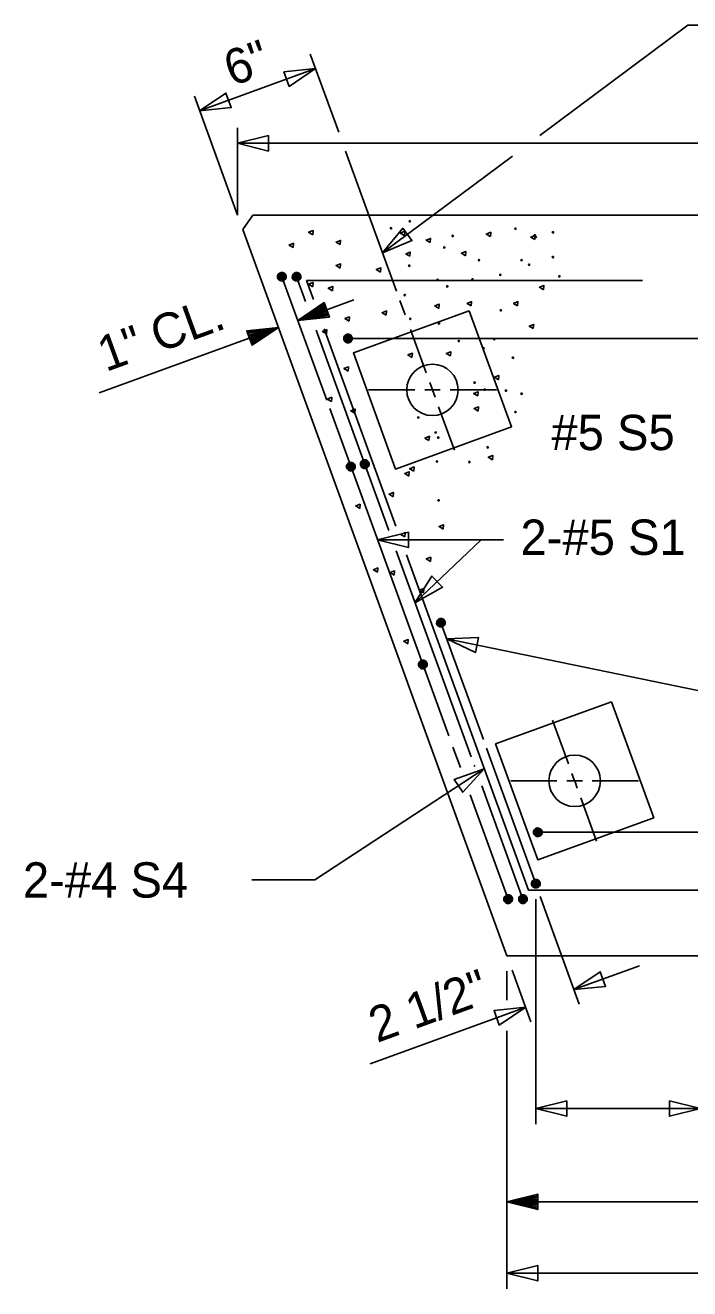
# Model space of a CAD drawing. Extents: x -408 to -23, y -15 to 117.
# Drawn here: x -111.83 to -109.13, y 76.34 to 81.46 of the extents above; entities that cross this region are included whole.
import ezdxf

# ---------------------------------------------------------------- set-up
doc = ezdxf.new("R2010")
doc.units = 0
for name, color, linetype in [('Arrowhead Terminators CELL', 7, 'Continuous'), ('Dimension Lines', 7, 'Continuous'), ('Rebar Lines', 7, 'Continuous'), ('Sup Concrete Girder Lines', 7, 'Continuous'), ('Sup Cored Slab Unit', 7, 'Continuous'), ('Text', 7, 'Continuous')]:
    doc.layers.add(name, color=color, linetype=linetype)

msp = doc.modelspace()

# ---------------------------------------------------------------- linework, layer by layer
at = {"layer": 'Arrowhead Terminators CELL'}
for points in [[(-110.6484, 81.2858), (-110.7766, 81.2724), (-110.7552, 81.2137)], [(-111.1183, 81.1148), (-110.9901, 81.1282), (-111.0115, 81.1869)], [(-110.9648, 80.9833), (-110.8398, 80.9521), (-110.8398, 81.0146)], [(-110.3768, 80.5394), (-110.2579, 80.589), (-110.2952, 80.6391)], [(-110.3973, 79.377), (-110.2722, 79.3458), (-110.2723, 79.4083)], [(-110.2459, 79.1216), (-110.1339, 79.1852), (-110.1769, 79.2304)], [(-110.1166, 78.9762), (-110.0005, 78.9204), (-109.9879, 78.9816)], [(-109.9649, 78.4494), (-110.0866, 78.407), (-110.0523, 78.3548)], [(-109.6013, 77.5554), (-109.4731, 77.5688), (-109.4945, 77.6276)], [(-109.797, 77.4842), (-109.9251, 77.4708), (-109.9038, 77.4121)], [(-109.7557, 77.0737), (-109.6307, 77.0425), (-109.6307, 77.105)], [(-109.089, 77.0737), (-109.214, 77.105), (-109.214, 77.0425)], [(-109.8729, 76.407), (-109.7479, 76.3758), (-109.7479, 76.4383)]]:
    msp.add_lwpolyline(points, close=True, dxfattribs=at)
at = {"layer": 'Dimension Lines'}
for p, q in [((-110.5546, 81.0279), (-110.6699, 81.3445)), ((-110.6484, 81.2858), (-111.1183, 81.1148)), ((-110.9648, 80.6929), (-111.1396, 81.1736)), ((-110.9648, 80.6929), (-110.9648, 81.0458)), ((-107.1729, 80.9833), (-110.9648, 80.9833)), ((-110.3202, 80.3839), (-110.5267, 80.9513)), ((-110.4934, 80.3487), (-110.7207, 80.2659)), ((-110.2854, 80.2881), (-110.3068, 80.3468)), ((-111.526, 79.9727), (-110.7989, 80.2374)), ((-110.1997, 80.0532), (-110.2639, 80.2293)), ((-110.2463, 79.9846), (-110.4338, 79.9845)), ((-109.9157, 79.9845), (-110.1032, 79.9845)), ((-110.0857, 79.7398), (-110.1498, 79.9159)), ((-110.3973, 79.377), (-109.9775, 79.377)), ((-109.6237, 78.4701), (-109.6879, 78.6462)), ((-109.6703, 78.4015), (-109.8578, 78.4014)), ((-109.3396, 78.4014), (-109.5272, 78.4014)), ((-109.5096, 78.1566), (-109.5738, 78.3328)), ((-109.7557, 77.0107), (-109.7557, 77.922)), ((-109.5799, 77.4967), (-109.7386, 77.933)), ((-109.8729, 77.5127), (-109.8729, 77.6304)), ((-109.7756, 77.4254), (-109.8515, 77.6341)), ((-109.6013, 77.5554), (-109.3359, 77.652)), ((-110.427, 77.2549), (-109.797, 77.4842)), ((-109.8729, 76.344), (-109.8729, 77.3892)), ((-109.7557, 77.0737), (-109.089, 77.0737)), ((-109.8729, 76.6958), (-107.4145, 76.6958)), ((-109.8729, 76.407), (-106.8729, 76.407))]:
    msp.add_line(p, q, dxfattribs=at)
for points in [[(-109.739, 81.0148), (-109.1398, 81.4614), (-108.5808, 81.4614)], [(-110.3768, 80.5394), (-109.8503, 80.9318)], [(-110.6033, 80.3086), (-110.6011, 80.3028), (-110.7207, 80.2659), (-110.5989, 80.2969), (-110.5968, 80.291), (-110.7207, 80.2659), (-110.5947, 80.2852), (-110.5926, 80.2793), (-110.7207, 80.2659), (-110.614, 80.338), (-110.6118, 80.3321), (-110.7207, 80.2659), (-110.6097, 80.3262), (-110.6075, 80.3203), (-110.7207, 80.2659), (-110.6054, 80.3145), (-110.5926, 80.2793), (-110.614, 80.338), (-110.7207, 80.2659), (-110.5926, 80.2793)], [(-110.9165, 80.1946), (-110.9186, 80.2004), (-110.7989, 80.2374), (-110.9208, 80.2064), (-110.923, 80.2123), (-110.7989, 80.2374), (-110.925, 80.2181), (-110.9271, 80.224), (-110.7989, 80.2374), (-110.9058, 80.1653), (-110.9079, 80.1712), (-110.7989, 80.2374), (-110.91, 80.1771), (-110.9121, 80.1829), (-110.7989, 80.2374), (-110.9144, 80.1887), (-110.9271, 80.224), (-110.9058, 80.1653), (-110.7989, 80.2374), (-110.9271, 80.224)], [(-110.1856, 80.014), (-110.1748, 79.9845), (-110.2063, 79.9844)], [(-110.1638, 79.9549), (-110.1745, 79.9843), (-110.1431, 79.9844)], [(-110.2459, 79.1216), (-109.9775, 79.377), (-109.8866, 79.377)], [(-110.1166, 78.9762), (-106.0469, 78.1387), (-105.9449, 78.1387)], [(-110.907, 77.9997), (-110.651, 77.9997), (-109.9649, 78.4494)], [(-109.6096, 78.4308), (-109.5987, 78.4014), (-109.6303, 78.4013)], [(-109.5877, 78.3717), (-109.5984, 78.4012), (-109.567, 78.4013)], [(-109.7479, 76.6958), (-109.7479, 76.6896), (-109.8729, 76.6958), (-109.7479, 76.6833), (-109.7479, 76.6771), (-109.8729, 76.6958), (-109.7479, 76.6708), (-109.7479, 76.6646), (-109.8729, 76.6958), (-109.7479, 76.7271), (-109.7479, 76.7208), (-109.8729, 76.6958), (-109.7479, 76.7146), (-109.7479, 76.7083), (-109.8729, 76.6958), (-109.7479, 76.7021), (-109.7479, 76.6646), (-109.7479, 76.7271), (-109.8729, 76.6958), (-109.7479, 76.6646)]]:
    msp.add_lwpolyline(points, dxfattribs=at)
at = {"layer": 'Rebar Lines'}
for p, q in [((-110.6033, 79.9433), (-110.7851, 80.4429)), ((-110.6887, 80.3419), (-110.7254, 80.4429)), ((-109.3238, 80.4273), (-110.6848, 80.4273)), ((-110.6569, 80.3505), (-110.6848, 80.4273)), ((-110.351, 79.4144), (-110.6467, 80.2269)), ((-110.3227, 79.4324), (-110.6136, 80.2316)), ((-110.5172, 80.1929), (-107.8297, 80.1929)), ((-110.4114, 79.416), (-110.591, 79.9094)), ((-110.1086, 78.5839), (-110.4115, 79.416)), ((-110.0179, 78.499), (-110.3214, 79.3331)), ((-109.7862, 77.9585), (-110.2806, 79.3167)), ((-109.9684, 78.5691), (-110.1405, 79.0417)), ((-110.0617, 78.4551), (-110.0919, 78.5381)), ((-109.7557, 77.9845), (-109.9555, 78.5333)), ((-110.0036, 78.4597), (-110.0056, 78.4652)), ((-109.8079, 77.922), (-109.9749, 78.3808)), ((-109.8677, 77.922), (-110.0216, 78.3449)), ((-109.7477, 78.1929), (-107.0602, 78.1929)), ((-108.4252, 77.9585), (-109.7862, 77.9585))]:
    msp.add_line(p, q, dxfattribs=at)
for points in [[(-110.8025, 80.4399), (-110.8024, 80.4467), (-110.7996, 80.453), (-110.7946, 80.4578), (-110.7882, 80.4602), (-110.7813, 80.4601), (-110.775, 80.4573), (-110.7703, 80.4524), (-110.7678, 80.446), (-110.7679, 80.4391), (-110.7707, 80.4328), (-110.7756, 80.428), (-110.782, 80.4255), (-110.789, 80.4257), (-110.7952, 80.4285), (-110.8, 80.4334), (-110.8025, 80.4399), (-110.7851, 80.4429), (-110.7678, 80.446), (-110.7703, 80.4524), (-110.7851, 80.4429), (-110.775, 80.4573), (-110.7813, 80.4601), (-110.7851, 80.4429), (-110.7882, 80.4602), (-110.7946, 80.4578), (-110.7851, 80.4429), (-110.7996, 80.453), (-110.8024, 80.4467), (-110.7851, 80.4429), (-110.8, 80.4334), (-110.7952, 80.4285), (-110.7851, 80.4429), (-110.789, 80.4257), (-110.782, 80.4255), (-110.7851, 80.4429), (-110.7756, 80.428), (-110.7707, 80.4328), (-110.7851, 80.4429), (-110.7679, 80.4391)], [(-110.7427, 80.4398), (-110.7426, 80.4466), (-110.7399, 80.4529), (-110.7349, 80.4577), (-110.7284, 80.4602), (-110.7216, 80.4601), (-110.7153, 80.4573), (-110.7105, 80.4524), (-110.708, 80.4459), (-110.7082, 80.4391), (-110.7109, 80.4328), (-110.7158, 80.428), (-110.7223, 80.4255), (-110.7292, 80.4256), (-110.7354, 80.4284), (-110.7402, 80.4333), (-110.7427, 80.4398), (-110.7254, 80.4429), (-110.708, 80.4459), (-110.7105, 80.4524), (-110.7254, 80.4429), (-110.7153, 80.4573), (-110.7216, 80.4601), (-110.7254, 80.4429), (-110.7284, 80.4602), (-110.7349, 80.4577), (-110.7254, 80.4429), (-110.7399, 80.4529), (-110.7426, 80.4466), (-110.7254, 80.4429), (-110.7402, 80.4333), (-110.7354, 80.4284), (-110.7254, 80.4429), (-110.7292, 80.4256), (-110.7223, 80.4255), (-110.7254, 80.4429), (-110.7158, 80.428), (-110.7109, 80.4328), (-110.7254, 80.4429), (-110.7082, 80.4391)], [(-110.5345, 80.1898), (-110.5343, 80.1967), (-110.5316, 80.203), (-110.5266, 80.2078), (-110.5202, 80.2102), (-110.5134, 80.2101), (-110.5071, 80.2073), (-110.5023, 80.2024), (-110.4998, 80.196), (-110.5, 80.1891), (-110.5027, 80.1828), (-110.5076, 80.178), (-110.5141, 80.1755), (-110.521, 80.1756), (-110.5272, 80.1784), (-110.532, 80.1834), (-110.5345, 80.1898), (-110.5172, 80.1929), (-110.4998, 80.196), (-110.5023, 80.2024), (-110.5172, 80.1929), (-110.5071, 80.2073), (-110.5134, 80.2101), (-110.5172, 80.1929), (-110.5202, 80.2102), (-110.5266, 80.2078), (-110.5172, 80.1929), (-110.5316, 80.203), (-110.5343, 80.1967), (-110.5172, 80.1929), (-110.532, 80.1834), (-110.5272, 80.1784), (-110.5172, 80.1929), (-110.521, 80.1756), (-110.5141, 80.1755), (-110.5172, 80.1929), (-110.5076, 80.178), (-110.5027, 80.1828), (-110.5172, 80.1929), (-110.5, 80.1891)], [(-110.5226, 79.6708), (-110.5225, 79.6777), (-110.5197, 79.684), (-110.5148, 79.6888), (-110.5083, 79.6912), (-110.5015, 79.6911), (-110.4952, 79.6883), (-110.4904, 79.6834), (-110.4879, 79.6769), (-110.4881, 79.6701), (-110.4908, 79.6638), (-110.4957, 79.659), (-110.5022, 79.6565), (-110.5091, 79.6567), (-110.5153, 79.6594), (-110.5201, 79.6644), (-110.5226, 79.6708), (-110.5053, 79.6739), (-110.4879, 79.6769), (-110.4904, 79.6834), (-110.5053, 79.6739), (-110.4952, 79.6883), (-110.5015, 79.6911), (-110.5053, 79.6739), (-110.5083, 79.6912), (-110.5148, 79.6888), (-110.5053, 79.6739), (-110.5197, 79.684), (-110.5225, 79.6777), (-110.5053, 79.6739), (-110.5201, 79.6644), (-110.5153, 79.6594), (-110.5053, 79.6739), (-110.5091, 79.6567), (-110.5022, 79.6565), (-110.5053, 79.6739), (-110.4957, 79.659), (-110.4908, 79.6638), (-110.5053, 79.6739), (-110.4881, 79.6701)], [(-110.4664, 79.6807), (-110.4663, 79.6876), (-110.4636, 79.6939), (-110.4586, 79.6987), (-110.4521, 79.7011), (-110.4453, 79.701), (-110.439, 79.6982), (-110.4343, 79.6933), (-110.4317, 79.6868), (-110.4319, 79.68), (-110.4346, 79.6737), (-110.4396, 79.6689), (-110.446, 79.6664), (-110.4529, 79.6666), (-110.4592, 79.6693), (-110.464, 79.6743), (-110.4664, 79.6807), (-110.4491, 79.6838), (-110.4317, 79.6868), (-110.4343, 79.6933), (-110.4491, 79.6838), (-110.439, 79.6982), (-110.4453, 79.701), (-110.4491, 79.6838), (-110.4521, 79.7011), (-110.4586, 79.6987), (-110.4491, 79.6838), (-110.4636, 79.6939), (-110.4663, 79.6876), (-110.4491, 79.6838), (-110.464, 79.6743), (-110.4592, 79.6693), (-110.4491, 79.6838), (-110.4529, 79.6666), (-110.446, 79.6664), (-110.4491, 79.6838), (-110.4396, 79.6689), (-110.4346, 79.6737), (-110.4491, 79.6838), (-110.4319, 79.68)], [(-110.1578, 79.0387), (-110.1577, 79.0455), (-110.155, 79.0518), (-110.15, 79.0566), (-110.1436, 79.059), (-110.1367, 79.0589), (-110.1304, 79.0561), (-110.1256, 79.0512), (-110.1231, 79.0448), (-110.1233, 79.0379), (-110.1261, 79.0316), (-110.131, 79.0268), (-110.1374, 79.0243), (-110.1443, 79.0245), (-110.1506, 79.0273), (-110.1554, 79.0322), (-110.1578, 79.0387), (-110.1405, 79.0417), (-110.1231, 79.0448), (-110.1256, 79.0512), (-110.1405, 79.0417), (-110.1304, 79.0561), (-110.1367, 79.0589), (-110.1405, 79.0417), (-110.1436, 79.059), (-110.15, 79.0566), (-110.1405, 79.0417), (-110.155, 79.0518), (-110.1577, 79.0455), (-110.1405, 79.0417), (-110.1554, 79.0322), (-110.1506, 79.0273), (-110.1405, 79.0417), (-110.1443, 79.0245), (-110.1374, 79.0243), (-110.1405, 79.0417), (-110.131, 79.0268), (-110.1261, 79.0316), (-110.1405, 79.0417), (-110.1233, 79.0379)], [(-110.2309, 78.8692), (-110.2308, 78.8761), (-110.228, 78.8824), (-110.223, 78.8872), (-110.2166, 78.8896), (-110.2098, 78.8895), (-110.2034, 78.8867), (-110.1987, 78.8818), (-110.1962, 78.8754), (-110.1964, 78.8685), (-110.1991, 78.8622), (-110.2041, 78.8574), (-110.2105, 78.8549), (-110.2174, 78.8551), (-110.2237, 78.8578), (-110.2284, 78.8628), (-110.2309, 78.8692), (-110.2136, 78.8723), (-110.1962, 78.8754), (-110.1987, 78.8818), (-110.2136, 78.8723), (-110.2034, 78.8867), (-110.2098, 78.8895), (-110.2136, 78.8723), (-110.2166, 78.8896), (-110.223, 78.8872), (-110.2136, 78.8723), (-110.228, 78.8824), (-110.2308, 78.8761), (-110.2136, 78.8723), (-110.2284, 78.8628), (-110.2237, 78.8578), (-110.2136, 78.8723), (-110.2174, 78.8551), (-110.2105, 78.8549), (-110.2136, 78.8723), (-110.2041, 78.8574), (-110.1991, 78.8622), (-110.2136, 78.8723), (-110.1964, 78.8685)], [(-109.765, 78.1898), (-109.7649, 78.1967), (-109.7621, 78.203), (-109.7572, 78.2078), (-109.7507, 78.2102), (-109.7439, 78.2101), (-109.7376, 78.2073), (-109.7329, 78.2024), (-109.7304, 78.196), (-109.7305, 78.1891), (-109.7333, 78.1828), (-109.7382, 78.178), (-109.7446, 78.1755), (-109.7515, 78.1756), (-109.7578, 78.1784), (-109.7626, 78.1834), (-109.765, 78.1898), (-109.7477, 78.1929), (-109.7304, 78.196), (-109.7329, 78.2024), (-109.7477, 78.1929), (-109.7376, 78.2073), (-109.7439, 78.2101), (-109.7477, 78.1929), (-109.7507, 78.2102), (-109.7572, 78.2078), (-109.7477, 78.1929), (-109.7621, 78.203), (-109.7649, 78.1967), (-109.7477, 78.1929), (-109.7626, 78.1834), (-109.7578, 78.1784), (-109.7477, 78.1929), (-109.7515, 78.1756), (-109.7446, 78.1755), (-109.7477, 78.1929), (-109.7382, 78.178), (-109.7333, 78.1828), (-109.7477, 78.1929), (-109.7305, 78.1891)], [(-109.773, 77.9814), (-109.7729, 77.9883), (-109.7702, 77.9946), (-109.7652, 77.9994), (-109.7588, 78.0018), (-109.7519, 78.0017), (-109.7456, 77.9989), (-109.7409, 77.994), (-109.7383, 77.9876), (-109.7386, 77.9807), (-109.7413, 77.9744), (-109.7462, 77.9696), (-109.7526, 77.9671), (-109.7595, 77.9673), (-109.7658, 77.97), (-109.7706, 77.975), (-109.773, 77.9814), (-109.7557, 77.9845), (-109.7383, 77.9876), (-109.7409, 77.994), (-109.7557, 77.9845), (-109.7456, 77.9989), (-109.7519, 78.0017), (-109.7557, 77.9845), (-109.7588, 78.0018), (-109.7652, 77.9994), (-109.7557, 77.9845), (-109.7702, 77.9946), (-109.7729, 77.9883), (-109.7557, 77.9845), (-109.7706, 77.975), (-109.7658, 77.97), (-109.7557, 77.9845), (-109.7595, 77.9673), (-109.7526, 77.9671), (-109.7557, 77.9845), (-109.7462, 77.9696), (-109.7413, 77.9744), (-109.7557, 77.9845), (-109.7386, 77.9807)], [(-109.885, 77.9189), (-109.8849, 77.9258), (-109.8821, 77.9321), (-109.8772, 77.9369), (-109.8707, 77.9393), (-109.8639, 77.9392), (-109.8576, 77.9364), (-109.8529, 77.9315), (-109.8504, 77.9251), (-109.8505, 77.9182), (-109.8533, 77.9119), (-109.8582, 77.9071), (-109.8646, 77.9046), (-109.8715, 77.9048), (-109.8778, 77.9075), (-109.8826, 77.9125), (-109.885, 77.9189), (-109.8677, 77.922), (-109.8504, 77.9251), (-109.8529, 77.9315), (-109.8677, 77.922), (-109.8576, 77.9364), (-109.8639, 77.9392), (-109.8677, 77.922), (-109.8707, 77.9393), (-109.8772, 77.9369), (-109.8677, 77.922), (-109.8821, 77.9321), (-109.8849, 77.9258), (-109.8677, 77.922), (-109.8826, 77.9125), (-109.8778, 77.9075), (-109.8677, 77.922), (-109.8715, 77.9048), (-109.8646, 77.9046), (-109.8677, 77.922), (-109.8582, 77.9071), (-109.8533, 77.9119), (-109.8677, 77.922), (-109.8505, 77.9182)], [(-109.8253, 77.919), (-109.8251, 77.9258), (-109.8224, 77.9321), (-109.8174, 77.9369), (-109.8109, 77.9393), (-109.8041, 77.9392), (-109.7978, 77.9364), (-109.7931, 77.9315), (-109.7906, 77.9251), (-109.7907, 77.9182), (-109.7935, 77.9119), (-109.7984, 77.9071), (-109.8049, 77.9046), (-109.8117, 77.9048), (-109.818, 77.9076), (-109.8228, 77.9125), (-109.8253, 77.919), (-109.8079, 77.922), (-109.7906, 77.9251), (-109.7931, 77.9315), (-109.8079, 77.922), (-109.7978, 77.9364), (-109.8041, 77.9392), (-109.8079, 77.922), (-109.8109, 77.9393), (-109.8174, 77.9369), (-109.8079, 77.922), (-109.8224, 77.9321), (-109.8251, 77.9258), (-109.8079, 77.922), (-109.8228, 77.9125), (-109.818, 77.9076), (-109.8079, 77.922), (-109.8117, 77.9048), (-109.8049, 77.9046), (-109.8079, 77.922), (-109.7984, 77.9071), (-109.7935, 77.9119), (-109.8079, 77.922), (-109.7907, 77.9182)]]:
    msp.add_lwpolyline(points, dxfattribs=at)
at = {"layer": 'Sup Concrete Girder Lines'}
for p, q in [((-110.9023, 80.6929), (-110.9434, 80.6341)), ((-110.9023, 80.6929), (-106.1295, 80.6929)), ((-109.8729, 77.6929), (-110.9434, 80.6341)), ((-109.8729, 77.6929), (-106.1295, 77.6929))]:
    msp.add_line(p, q, dxfattribs=at)
for points in [[(-110.66, 80.6128), (-110.6586, 80.6301), (-110.6765, 80.6229), (-110.66, 80.6128)], [(-110.2885, 80.6096), (-110.287, 80.6268), (-110.305, 80.6197), (-110.2885, 80.6096)], [(-109.9402, 80.6055), (-109.9387, 80.6228), (-109.9567, 80.6156), (-109.9402, 80.6055)], [(-109.7599, 80.5932), (-109.7584, 80.6105), (-109.7764, 80.6033), (-109.7599, 80.5932)], [(-110.7395, 80.5612), (-110.738, 80.5785), (-110.756, 80.5713), (-110.7395, 80.5612)], [(-110.5488, 80.5731), (-110.5473, 80.5903), (-110.5653, 80.5832), (-110.5488, 80.5731)], [(-110.184, 80.5809), (-110.1826, 80.5981), (-110.2005, 80.591), (-110.184, 80.5809)], [(-110.2659, 80.5256), (-110.2645, 80.5428), (-110.2825, 80.5357), (-110.2659, 80.5256)], [(-110.0406, 80.5277), (-110.0391, 80.5449), (-110.0571, 80.5378), (-110.0406, 80.5277)], [(-110.5488, 80.4778), (-110.5473, 80.495), (-110.5653, 80.4879), (-110.5488, 80.4778)], [(-110.3858, 80.4618), (-110.3844, 80.4791), (-110.4024, 80.4719), (-110.3858, 80.4618)], [(-110.66, 80.4023), (-110.6586, 80.4195), (-110.6765, 80.4124), (-110.66, 80.4023)], [(-110.5805, 80.3864), (-110.5791, 80.4036), (-110.597, 80.3965), (-110.5805, 80.3864)], [(-109.7251, 80.3904), (-109.7236, 80.4076), (-109.7416, 80.4005), (-109.7251, 80.3904)], [(-110.362, 80.287), (-110.3606, 80.3043), (-110.3786, 80.2971), (-110.362, 80.287)], [(-110.1492, 80.3145), (-110.1477, 80.3318), (-110.1657, 80.3246), (-110.1492, 80.3145)], [(-110.018, 80.3248), (-110.0166, 80.342), (-110.0345, 80.3349), (-110.018, 80.3248)], [(-109.8295, 80.3248), (-109.8281, 80.342), (-109.8461, 80.3349), (-109.8295, 80.3248)], [(-110.513, 80.2632), (-110.5115, 80.2804), (-110.5295, 80.2733), (-110.513, 80.2632)], [(-109.766, 80.2326), (-109.7645, 80.2499), (-109.7825, 80.2427), (-109.766, 80.2326)], [(-110.6044, 80.2116), (-110.6029, 80.2288), (-110.6209, 80.2217), (-110.6044, 80.2116)], [(-110.102, 80.1219), (-110.1006, 80.1392), (-110.1186, 80.132), (-110.102, 80.1219)], [(-110.2578, 80.1158), (-110.2563, 80.133), (-110.2743, 80.1259), (-110.2578, 80.1158)], [(-110.517, 80.0606), (-110.5155, 80.0778), (-110.5335, 80.0707), (-110.517, 80.0606)], [(-109.9074, 80.0256), (-109.9059, 80.0429), (-109.9239, 80.0357), (-109.9074, 80.0256)], [(-110.5845, 79.9374), (-110.5831, 79.9546), (-110.6011, 79.9475), (-110.5845, 79.9374)], [(-109.9914, 79.9601), (-109.99, 79.9773), (-110.0079, 79.9702), (-109.9914, 79.9601)], [(-110.4892, 79.8898), (-110.4877, 79.907), (-110.5057, 79.8999), (-110.4892, 79.8898)], [(-109.9893, 79.8986), (-109.9879, 79.9158), (-110.0058, 79.9087), (-109.9893, 79.8986)], [(-110.1889, 79.7793), (-110.1874, 79.7966), (-110.2054, 79.7895), (-110.1889, 79.7793)], [(-109.932, 79.7019), (-109.9305, 79.7192), (-109.9485, 79.712), (-109.932, 79.7019)], [(-110.2706, 79.6354), (-110.2692, 79.6527), (-110.2871, 79.6455), (-110.2706, 79.6354)], [(-110.2508, 79.6553), (-110.2493, 79.6726), (-110.2673, 79.6654), (-110.2508, 79.6553)], [(-110.3342, 79.552), (-110.3328, 79.5692), (-110.3507, 79.5621), (-110.3342, 79.552)], [(-110.4693, 79.5043), (-110.4678, 79.5216), (-110.4858, 79.5144), (-110.4693, 79.5043)], [(-110.1316, 79.4209), (-110.1301, 79.4381), (-110.1481, 79.431), (-110.1316, 79.4209)], [(-110.2865, 79.3891), (-110.2851, 79.4064), (-110.303, 79.3992), (-110.2865, 79.3891)], [(-110.1832, 79.2898), (-110.1818, 79.307), (-110.1998, 79.2999), (-110.1832, 79.2898)], [(-110.3978, 79.2461), (-110.3963, 79.2633), (-110.4143, 79.2562), (-110.3978, 79.2461)], [(-110.3302, 79.2342), (-110.3288, 79.2514), (-110.3467, 79.2443), (-110.3302, 79.2342)], [(-110.2111, 79.1627), (-110.2096, 79.1799), (-110.2276, 79.1728), (-110.2111, 79.1627)], [(-110.2746, 78.9561), (-110.2731, 78.9733), (-110.2911, 78.9662), (-110.2746, 78.9561)]]:
    msp.add_lwpolyline(points, dxfattribs=at)
for centre, radius in [((-110.2665, 80.6678), 0.00273), ((-110.3423, 80.6391), 0.00273), ((-110.0924, 80.6084), 0.00273), ((-109.8383, 80.637), 0.00273), ((-109.7604, 80.6104), 0.00273), ((-109.7563, 80.6043), 0.00273), ((-109.6866, 80.6227), 0.00273), ((-110.1272, 80.5613), 0.00273), ((-109.9858, 80.51), 0.00273), ((-109.8137, 80.51), 0.00273), ((-109.6866, 80.5223), 0.00273), ((-110.2686, 80.4874), 0.00273), ((-109.8998, 80.4506), 0.00273), ((-109.7829, 80.4916), 0.00273), ((-109.66, 80.4444), 0.00273), ((-110.1538, 80.4301), 0.00273), ((-110.1149, 80.4035), 0.00273), ((-110.0125, 80.4321), 0.00273), ((-110.287, 80.3686), 0.00273), ((-109.8977, 80.3072), 0.00273), ((-110.2644, 80.2723), 0.00273), ((-110.1477, 80.2539), 0.00273), ((-109.9243, 80.1904), 0.00273), ((-110.0678, 80.1822), 0.00273), ((-109.9674, 80.1535), 0.00273), ((-110.1748, 79.9846), 0.1042), ((-109.8485, 80.1146), 0.00273), ((-110.0042, 80.0142), 0.00273), ((-109.9632, 79.9855), 0.00273), ((-109.8772, 79.9814), 0.00273), ((-109.8137, 79.9691), 0.00273), ((-109.8383, 79.8953), 0.00273), ((-110.2317, 79.8728), 0.00273), ((-110.1616, 79.812), 0.00273), ((-110.1513, 79.7915), 0.00273), ((-109.9509, 79.7519), 0.00273), ((-110.1558, 79.6945), 0.00273), ((-110.0248, 79.6925), 0.00273), ((-110.1497, 79.5368), 0.00273), ((-109.5984, 78.4012), 0.1042)]:
    msp.add_circle(centre, radius, dxfattribs=at)
at = {"layer": 'Sup Cored Slab Unit'}
for points in [[(-110.0254, 80.305), (-110.4952, 80.134), (-110.3242, 79.6641), (-109.8543, 79.8351)], [(-109.449, 78.7216), (-109.9189, 78.5506), (-109.7478, 78.0808), (-109.278, 78.2518)]]:
    msp.add_lwpolyline(points, close=True, dxfattribs=at)

# ---------------------------------------------------------------- texts
at = {"layer": 'Text'}
for s, rotation, p in [('6"', 19.9877, (-110.9865, 81.2129)), ('1" CL.', 20.0021, (-111.4983, 80.0566)), ('2 1/2"', 19.9967, (-110.3992, 77.3391))]:
    msp.add_text(s, height=0.14302, rotation=rotation, dxfattribs=at).set_placement(p)
for s, p in [('#5 S5', (-109.6928, 79.7406)), ('2-#5 S1', (-109.818, 79.3164)), ('2-#4 S4', (-111.8347, 77.9282))]:
    msp.add_text(s, height=0.14302, dxfattribs=at).set_placement(p)

doc.saveas('drawing.dxf')
